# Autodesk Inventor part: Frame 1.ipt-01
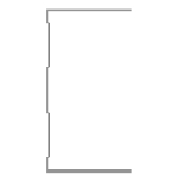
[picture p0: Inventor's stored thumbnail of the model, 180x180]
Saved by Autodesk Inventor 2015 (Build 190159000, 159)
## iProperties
Created: 2015-04
Part Number: Frame 1.ipt-01
Material: Aluminum 6061
Description: Kévin Novo
Document SubType Name: Modeling
Standard: Kevin
Designer: suporte
Standards Organization: Kevin
Language: en-US
Size Designation: (Unnamed 1)
Categories: <MemberInstance><Categories><Category DisplayName="Structural Shapes" InternalName="089c4875-fa83-4c05-b084-43b9cc11f5ed" Mnemonic="GRDR"><CategoryParameter Dis
Density: 2.7 g/cm^3
Appearance: Aluminum - Flat
_CCFamilyMember: 1
_CCFamilyDisplayName: Kévin - Kévin Novo
_FrameMemberDoc: Frame Member File
_Version: 15.0.0
_GetPNFromCC: 1
IsCustomPart: 1
Author: suporte
G_L: 1150,000 mm
G_W: 50,000 mm
G_H: 75,000 mm
+45B8A6D9-03A5-49AF-AB0C-45E396BDBBF2+CUTDETAIL1: Cut
+657C0FA2-9EC3-4FA9-9A37-8D1E4F84BB90+CUTDETAIL2: Cut
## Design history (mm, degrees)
node "Start Plane"
node "End Plane"
sketch "Sketch"
  geometry: L1 (24.7, 37.5)-(24.7, 36.9); L2 (24.7, 36.9)-(-24.7, 36.9); L3 (-24.7, -36.9)-(24.7, -36.9); L4 (24.7, -36.9)-(24.7, -37.5); L5 (24.7, -37.5)-(-25.3, -37.5); L6 (-25.3, 37.5)-(24.7, 37.5); L7 (-24.7, 36.9)-(-24.7, 31.9); L8 (-24.7, 31.9)-(-23.3, 30.5); L9 (-23.3, 30.5)-(-23.3, 10.934); L10 (-23.3, 10.934)-(-24.7, 9.534); L11 (-24.7, 9.534)-(-24.7, -9.534); L12 (-24.7, -9.534)-(-23.3, -10.934); L13 (-23.3, -10.934)-(-23.3, -30.5); L14 (-23.3, -30.5)-(-24.7, -31.9); L15 (-24.7, -31.9)-(-24.7, -36.9); L16 (-25.3, -37.5)-(-25.3, -31.651); L17 (-25.3, -31.651)-(-23.9, -30.251); L18 (-23.9, -30.251)-(-23.9, -11.183); L19 (-23.9, -11.183)-(-25.3, -9.783); L20 (-25.3, -9.783)-(-25.3, 9.783); L21 (-25.3, 9.783)-(-23.9, 11.183); L22 (-23.9, 11.183)-(-23.9, 30.251); L23 (-23.9, 30.251)-(-25.3, 31.651); L24 (-25.3, 31.651)-(-25.3, 37.5); L25 (-25.3, 0)-(30.37, 0); 3 further points
  constraints: 50 end point, 10 point on line, 9 parallel, 5 perpendicular, 4 equal length, 3 midpoint, 3 vertical, 2 vertical alignment, 1 collinear, 1 horizontal, 1 horizontal alignment
  dimensions: "d3" = 0.6 distance of L1.start L1.end (= d6); "d5" = 75 distance between parallel lines of L5 L6; "d6" = 0.6 distance between parallel lines of L24 L7 (= d8); "d7" = 0.6 distance between parallel lines of L8 L23 (= d8); "d8" = 0.6 distance between parallel lines of L22 L9 (= d12); "Espessura" = 0.6 distance between parallel lines of L17 L14; "d10" = 0.6 distance between parallel lines of L13 L18 (= Espessura); "d11" = 0.6 distance between parallel lines of L12 L19 (= Espessura); "d12" = 0.6 distance between parallel lines of L21 L10 (= d11); "d13" = 5 distance of L2.end L7.end; "d15" = 135 deg angle of L9 L8; "d16" = 2 distance between parallel lines of L24 L9; "d17" = 50 distance of L6.start L1.start
extrude "Body" join sketch "Sketch" stored distance "d24" = 0.13; taper "d25" = 0 deg
node "Driven Length"
  sketch "Sketch10"
    geometry: L1 (0, 0)-(10, 0) reference
    constraints: 2 end point, 1 horizontal
  workplane "Work Plane7"
  sketch "Sketch11"
    geometry: L1 (-2, 12.5)-(12, 12.5) reference; L2 (-2, 1162.5)-(12, 1162.5) reference
    dimensions: "d27" = 1150 distance between parallel lines of L1 L2 (derived)
workplane "Work Plane8"
split "Split1"
workplane "Work Plane9"
split "Split2"
body "Solid1"
other parameters: "G_OFFSET_START" = -12.5 [user parameter; used in 1 equation term], "G_OFFSET_END" = -37.5 [user parameter; used in 1 equation term], "d22" = 12.5 (= -G_OFFSET_START), "d23" = 1162.5 (= tamanho + G_OFFSET_END), "G_L" = 1150 (= d27) [user parameter], "d34" = 90 deg
